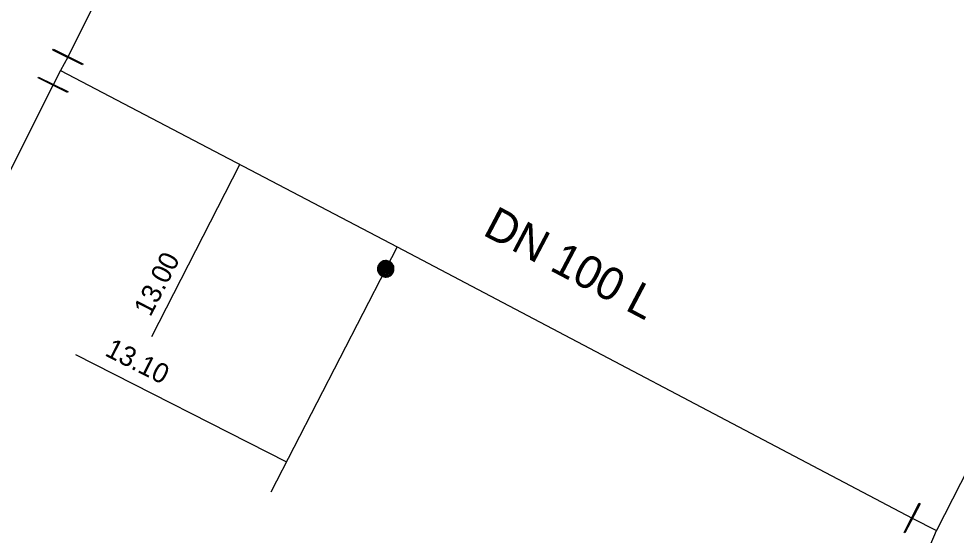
# Model space of a CAD drawing. Extents: x -820257 to -819974, y -1070894 to -1070484.
# Drawn here: x -820109.2 to -820052, y -1070665.6 to -1070634.2 of the extents above; entities that cross this region are included whole.
import ezdxf

# ---------------------------------------------------------------- set-up
doc = ezdxf.new("R2010")
doc.units = 0
for name, color, linetype in [('Oměrka vodovodu', 7, 'Continuous'), ('Oměrka-text', 7, 'Continuous'), ('Přípojka vodovodu', 7, 'Continuous'), ('Přípojkový uzávěr', 7, 'Continuous'), ('Roz-řad', 7, 'Continuous'), ('Roz-řad-popis základní', 7, 'Continuous'), ('Řad-šoupě', 7, 'Continuous')]:
    doc.layers.add(name, color=color, linetype=linetype)

msp = doc.modelspace()

# ---------------------------------------------------------------- linework, layer by layer
at = {"layer": 'Oměrka vodovodu'}
for p, q in [((-820101.072, -1070653.529), (-820095.709, -1070643.055)), ((-820105.736, -1070654.624), (-820092.867, -1070661.16))]:
    msp.add_line(p, q, dxfattribs=at)
at = {"layer": 'Přípojka vodovodu'}
msp.add_lwpolyline([(-820086.134, -1070648.072), (-820086.82, -1070649.406), (-820093.825, -1070663.023)], dxfattribs=at)
at = {"layer": 'Přípojkový uzávěr'}
for points in [[(-820087.266, -1070649.177), (-820087.208, -1070649.065), (-820087.096, -1070648.988), (-820086.984, -1070648.912), (-820086.846, -1070648.906), (-820086.708, -1070648.901), (-820086.592, -1070648.961), (-820086.476, -1070649.021), (-820086.401, -1070649.134), (-820086.325, -1070649.247), (-820086.321, -1070649.383), (-820086.317, -1070649.519), (-820086.377, -1070649.635), (-820086.436, -1070649.75), (-820086.549, -1070649.826), (-820086.662, -1070649.901), (-820086.798, -1070649.906), (-820086.934, -1070649.91), (-820087.049, -1070649.851), (-820087.166, -1070649.791), (-820087.242, -1070649.676), (-820087.318, -1070649.561), (-820087.321, -1070649.425), (-820087.324, -1070649.29), (-820087.266, -1070649.177)], [(-820087.224, -1070649.199), (-820087.276, -1070649.3), (-820087.274, -1070649.424), (-820087.272, -1070649.547), (-820087.202, -1070649.651), (-820087.133, -1070649.755), (-820087.028, -1070649.809), (-820086.923, -1070649.863), (-820086.8, -1070649.859), (-820086.677, -1070649.855), (-820086.574, -1070649.786), (-820086.472, -1070649.718), (-820086.418, -1070649.613), (-820086.364, -1070649.508), (-820086.368, -1070649.385), (-820086.372, -1070649.261), (-820086.44, -1070649.159), (-820086.509, -1070649.057), (-820086.613, -1070649.003), (-820086.719, -1070648.949), (-820086.844, -1070648.953), (-820086.969, -1070648.958), (-820087.07, -1070649.028), (-820087.172, -1070649.097), (-820087.224, -1070649.199)], [(-820087.194, -1070649.214), (-820087.145, -1070649.12), (-820087.052, -1070649.056), (-820086.958, -1070648.992), (-820086.842, -1070648.988), (-820086.727, -1070648.983), (-820086.629, -1070649.033), (-820086.532, -1070649.083), (-820086.469, -1070649.178), (-820086.405, -1070649.272), (-820086.402, -1070649.386), (-820086.399, -1070649.5), (-820086.449, -1070649.598), (-820086.498, -1070649.694), (-820086.593, -1070649.758), (-820086.688, -1070649.822), (-820086.802, -1070649.825), (-820086.915, -1070649.828), (-820087.012, -1070649.778), (-820087.11, -1070649.728), (-820087.174, -1070649.632), (-820087.238, -1070649.536), (-820087.24, -1070649.422), (-820087.242, -1070649.308), (-820087.194, -1070649.214)], [(-820087.155, -1070649.235), (-820087.226, -1070649.374), (-820087.178, -1070649.521), (-820087.131, -1070649.668), (-820086.992, -1070649.739), (-820086.854, -1070649.81), (-820086.706, -1070649.763), (-820086.558, -1070649.715), (-820086.488, -1070649.578), (-820086.416, -1070649.439), (-820086.464, -1070649.291), (-820086.511, -1070649.143), (-820086.649, -1070649.072), (-820086.787, -1070649.001), (-820086.935, -1070649.048), (-820087.083, -1070649.095), (-820087.155, -1070649.235)], [(-820087.114, -1070649.256), (-820087.051, -1070649.134), (-820086.922, -1070649.093), (-820086.793, -1070649.052), (-820086.672, -1070649.114), (-820086.551, -1070649.177), (-820086.51, -1070649.306), (-820086.468, -1070649.435), (-820086.53, -1070649.556), (-820086.593, -1070649.678), (-820086.722, -1070649.719), (-820086.851, -1070649.76), (-820086.972, -1070649.698), (-820087.093, -1070649.636), (-820087.135, -1070649.507), (-820087.177, -1070649.378), (-820087.114, -1070649.256)], [(-820087.079, -1070649.274), (-820087.134, -1070649.381), (-820087.097, -1070649.494), (-820087.061, -1070649.608), (-820086.954, -1070649.663), (-820086.848, -1070649.717), (-820086.734, -1070649.681), (-820086.621, -1070649.645), (-820086.566, -1070649.538), (-820086.511, -1070649.432), (-820086.547, -1070649.318), (-820086.584, -1070649.204), (-820086.69, -1070649.149), (-820086.797, -1070649.095), (-820086.91, -1070649.131), (-820087.024, -1070649.167), (-820087.079, -1070649.274)], [(-820087.043, -1070649.292), (-820086.995, -1070649.198), (-820086.897, -1070649.167), (-820086.799, -1070649.136), (-820086.706, -1070649.184), (-820086.614, -1070649.231), (-820086.583, -1070649.329), (-820086.551, -1070649.428), (-820086.599, -1070649.52), (-820086.646, -1070649.612), (-820086.744, -1070649.644), (-820086.843, -1070649.676), (-820086.935, -1070649.628), (-820087.027, -1070649.581), (-820087.059, -1070649.483), (-820087.091, -1070649.385), (-820087.043, -1070649.292)], [(-820087.002, -1070649.313), (-820087.041, -1070649.388), (-820087.015, -1070649.468), (-820086.99, -1070649.548), (-820086.914, -1070649.587), (-820086.839, -1070649.625), (-820086.759, -1070649.6), (-820086.68, -1070649.574), (-820086.641, -1070649.499), (-820086.603, -1070649.424), (-820086.628, -1070649.344), (-820086.654, -1070649.264), (-820086.729, -1070649.225), (-820086.804, -1070649.187), (-820086.884, -1070649.212), (-820086.964, -1070649.238), (-820087.002, -1070649.313)], [(-820086.971, -1070649.329), (-820086.939, -1070649.266), (-820086.873, -1070649.245), (-820086.807, -1070649.224), (-820086.744, -1070649.256), (-820086.682, -1070649.288), (-820086.661, -1070649.355), (-820086.64, -1070649.421), (-820086.672, -1070649.483), (-820086.704, -1070649.545), (-820086.77, -1070649.567), (-820086.836, -1070649.588), (-820086.899, -1070649.556), (-820086.961, -1070649.524), (-820086.982, -1070649.457), (-820087.004, -1070649.391), (-820086.971, -1070649.329)], [(-820086.932, -1070649.349), (-820086.956, -1070649.395), (-820086.94, -1070649.444), (-820086.924, -1070649.493), (-820086.878, -1070649.517), (-820086.832, -1070649.54), (-820086.783, -1070649.525), (-820086.733, -1070649.509), (-820086.71, -1070649.463), (-820086.686, -1070649.417), (-820086.702, -1070649.368), (-820086.718, -1070649.318), (-820086.764, -1070649.295), (-820086.81, -1070649.271), (-820086.859, -1070649.286), (-820086.908, -1070649.302), (-820086.932, -1070649.349)], [(-820086.891, -1070649.37), (-820086.875, -1070649.341), (-820086.845, -1070649.331), (-820086.815, -1070649.321), (-820086.785, -1070649.337), (-820086.757, -1070649.351), (-820086.747, -1070649.382), (-820086.736, -1070649.412), (-820086.752, -1070649.442), (-820086.766, -1070649.47), (-820086.797, -1070649.48), (-820086.828, -1070649.49), (-820086.857, -1070649.476), (-820086.886, -1070649.46), (-820086.896, -1070649.43), (-820086.905, -1070649.399), (-820086.891, -1070649.37)], [(-820086.863, -1070649.385), (-820086.872, -1070649.402), (-820086.866, -1070649.42), (-820086.86, -1070649.439), (-820086.843, -1070649.448), (-820086.825, -1070649.457), (-820086.807, -1070649.451), (-820086.788, -1070649.445), (-820086.779, -1070649.428), (-820086.77, -1070649.41), (-820086.776, -1070649.392), (-820086.782, -1070649.373), (-820086.8, -1070649.364), (-820086.817, -1070649.355), (-820086.836, -1070649.361), (-820086.854, -1070649.367), (-820086.863, -1070649.385)]]:
    msp.add_open_spline(points, degree=3, dxfattribs=at)
at = {"layer": 'Roz-řad'}
for p, q in [((-820106.194, -1070636.505), (-820106.646, -1070637.325)), ((-820106.646, -1070637.325), (-820107.099, -1070638.195)), ((-820054.738, -1070664.597), (-820053.253, -1070665.35)), ((-820053.629, -1070666.271), (-820053.253, -1070665.35))]:
    msp.add_line(p, q, dxfattribs=at)
for points in [[(-820097.577, -1070619.176), (-820098.566, -1070621.164), (-820106.194, -1070636.505)], [(-820016.74, -1070635.54), (-820049.836, -1070658.668), (-820053.253, -1070665.35)], [(-820106.646, -1070637.325), (-820086.134, -1070648.072), (-820054.738, -1070664.597)], [(-820107.099, -1070638.195), (-820120.711, -1070665.309), (-820144.508, -1070712.712)]]:
    msp.add_lwpolyline(points, dxfattribs=at)
at = {"layer": 'Řad-šoupě'}
for points in [[(-820107.075, -1070636.03), (-820105.284, -1070636.921), (-820105.312, -1070636.977), (-820107.103, -1070636.086), (-820107.075, -1070636.03)], [(-820107.98, -1070637.72), (-820106.189, -1070638.611), (-820106.217, -1070638.667), (-820108.008, -1070637.776), (-820107.98, -1070637.72)], [(-820054.243, -1070663.725), (-820055.175, -1070665.495), (-820055.23, -1070665.466), (-820054.299, -1070663.696), (-820054.243, -1070663.725)]]:
    msp.add_lwpolyline(points, dxfattribs=at)

# ---------------------------------------------------------------- texts
at = {"layer": 'Oměrka-text'}
for s, rotation, p in [('13.00', 62.8862, (-820101.167, -1070652.376)), ('13.10', 333.0746, (-820104.003, -1070654.657))]:
    msp.add_text(s, height=1.2, rotation=rotation, dxfattribs=at).set_placement(p)
at = {"layer": 'Roz-řad-popis základní'}
msp.add_text('DN 100 L', height=2, rotation=332.2403, dxfattribs=at).set_placement((-820080.979, -1070647.307))

doc.saveas('drawing.dxf')
